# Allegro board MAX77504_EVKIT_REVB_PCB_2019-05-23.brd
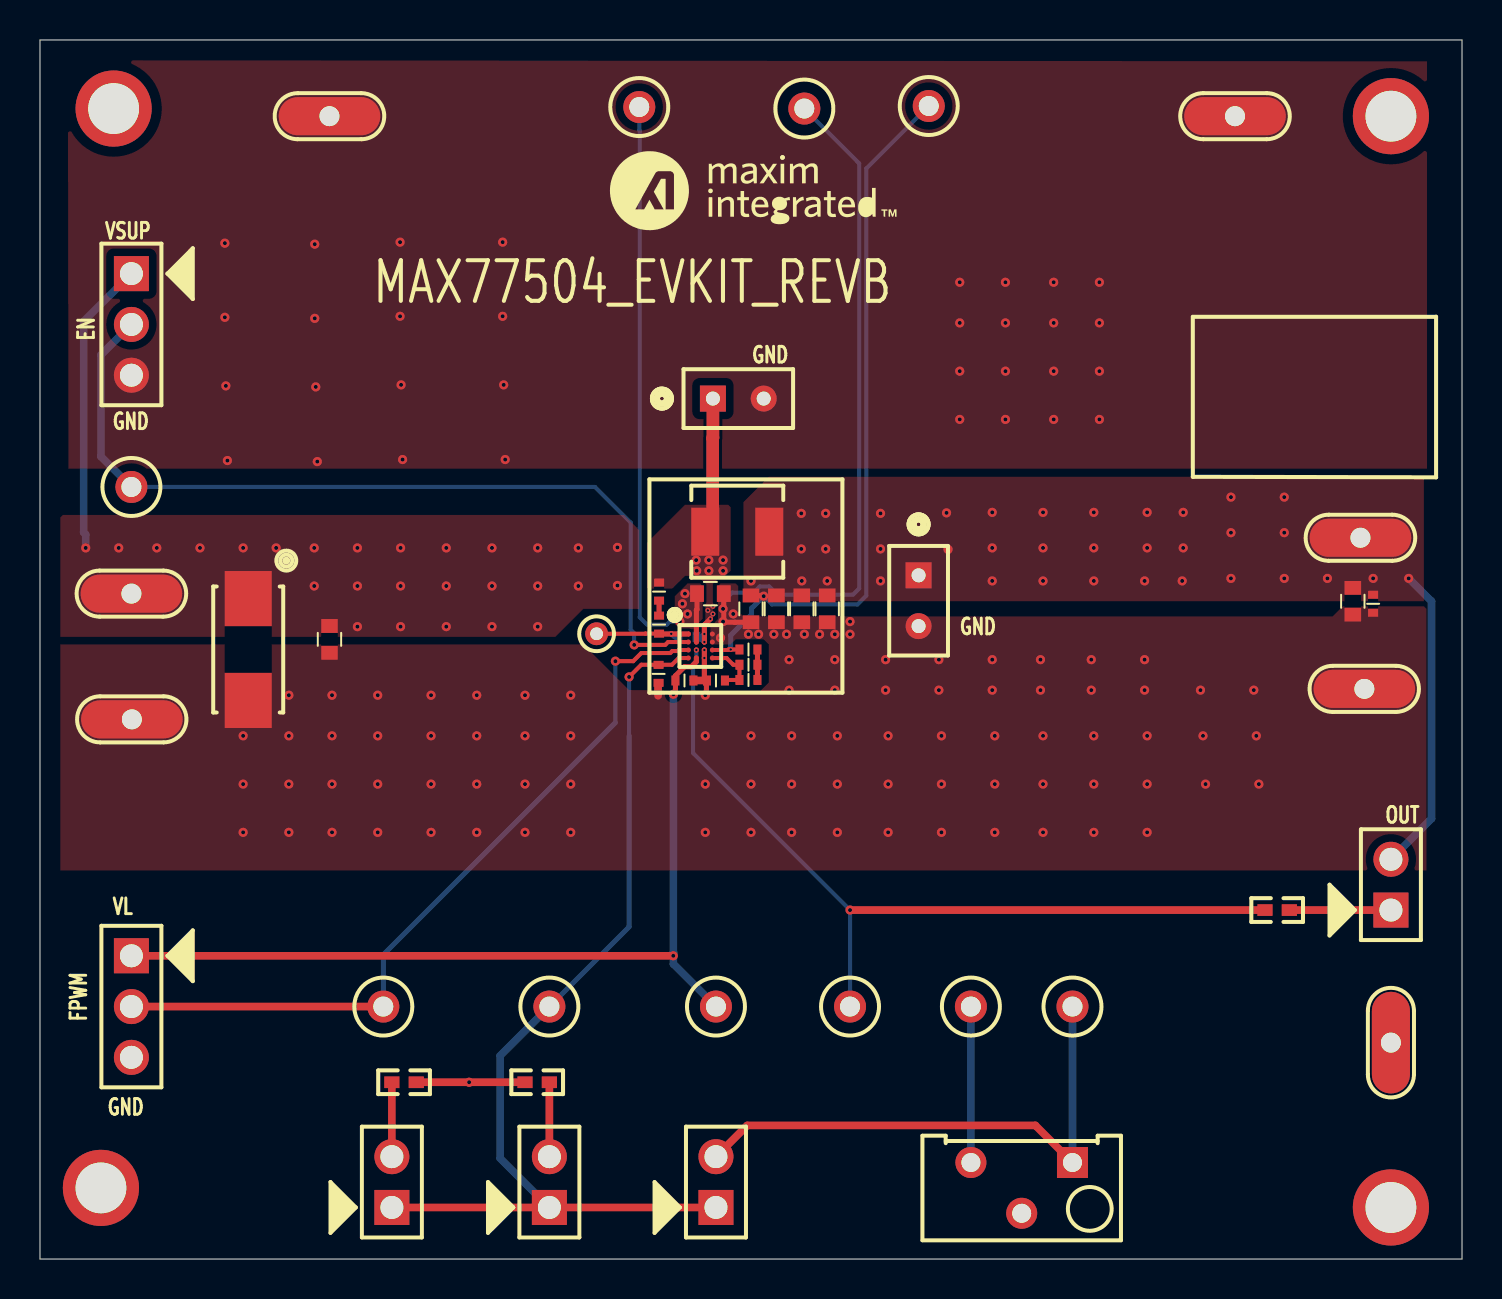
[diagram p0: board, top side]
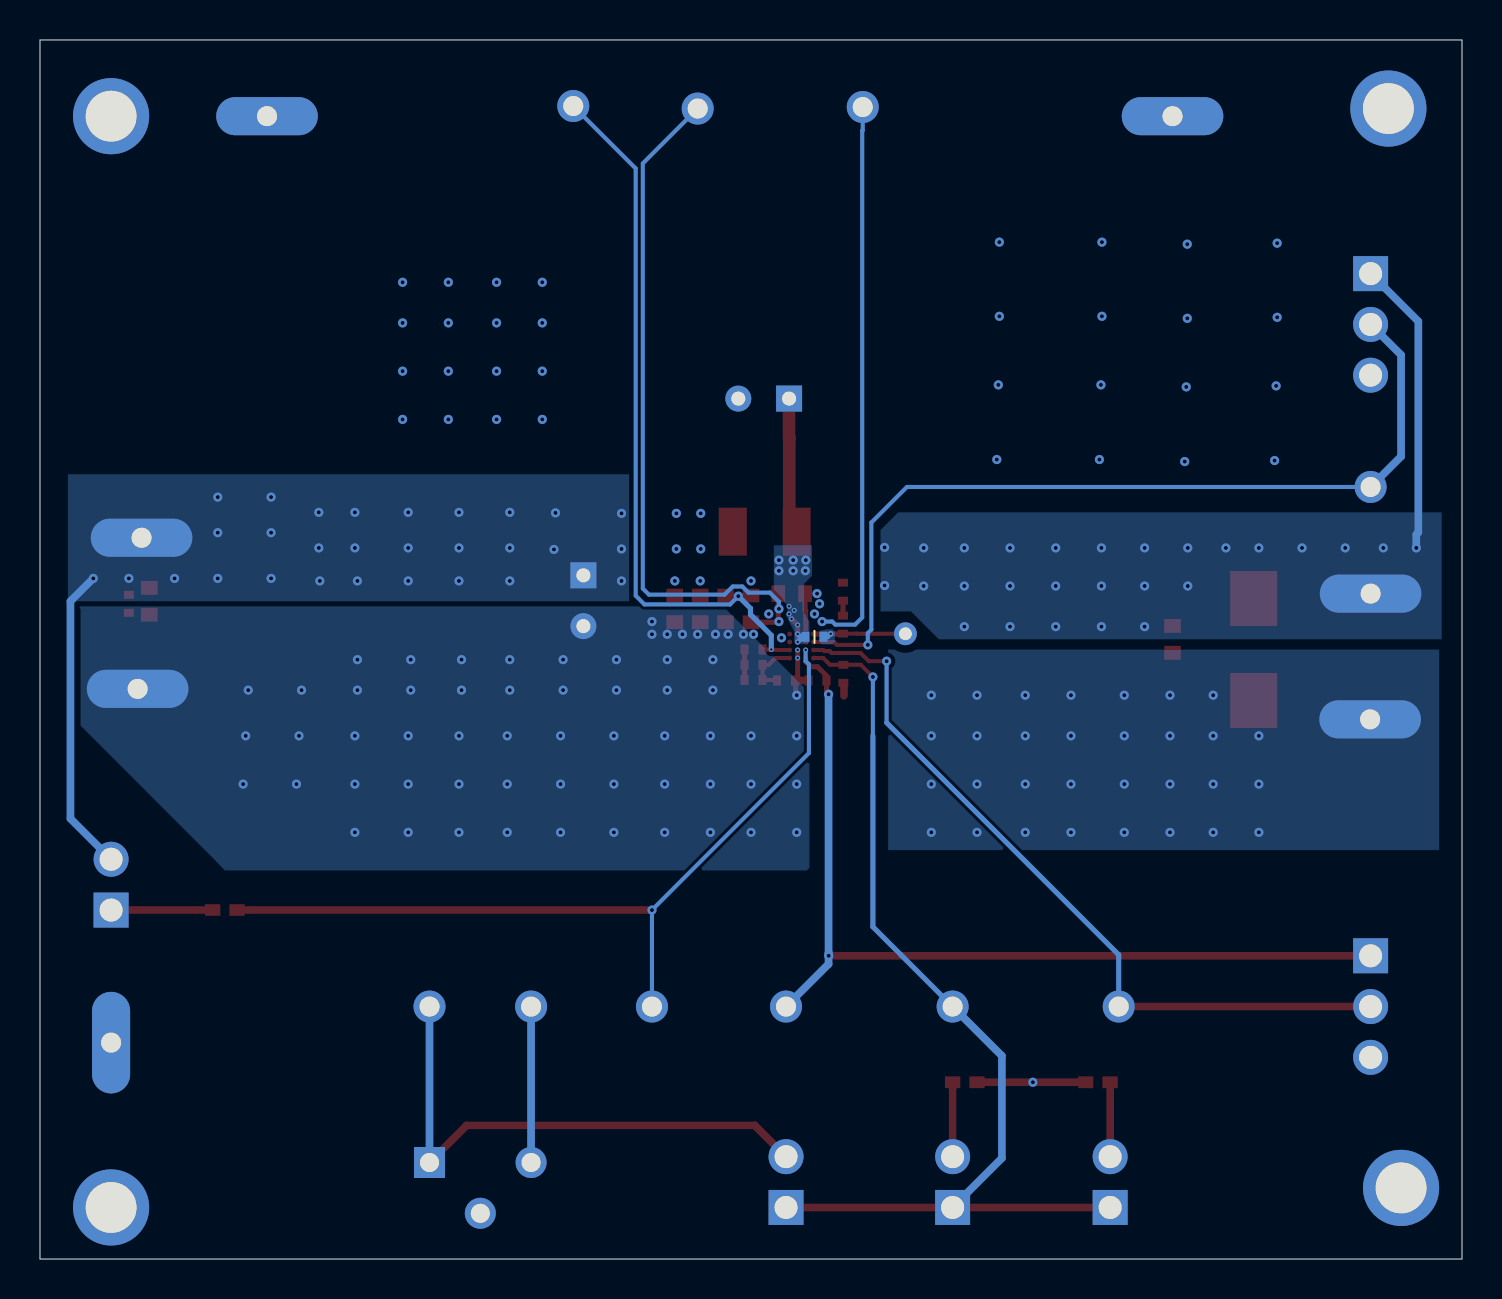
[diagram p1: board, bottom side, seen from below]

Outline 71.12 x 60.96 mm; copper layers: TOP, INTERNAL2, INTERNAL3, BOTTOM. Coordinates in mm from the lower left corner of the outline.
Outline path: 0,60.96 0,0 71.12,0 71.12,60.96 0,60.96

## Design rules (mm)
constraint set DEFAULT: min track width 0.254

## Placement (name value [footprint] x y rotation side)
BST  N/A  [TP_C114H63]  27.84 31.27 0 top
C1  10UF  [0603]  33.53 33.27 180 top
C2  OPEN  [CAPC1608X90L]  14.48 30.99 90 top
C3  2.2UF  [CAPC1005X50L]  32.23 28.93 180 top
C4  2.2PF  [0402]  35.43 29.72 0 top
C5  22UF  [CAPC1608X90L]  35.56 32.51 90 top
C6  22UF  [CAPC1608X90L]  36.83 32.51 90 top
C7  22UF  [CAPC1608X90L]  38.1 32.51 90 top
C8  OPEN  [CAPC1608X90L]  39.37 32.51 90 top
C9  0.1UF  [CAPC1005X50L]  66.67 32.77 90 top
C10  OPEN  [CAPC1608X90L]  65.66 32.89 90 top
C11  100UF  [CAPMP6032X280M]  10.41 30.48 270 top
C12  OPEN  [CAPC1005X50L]  32.38 31.11 180 bottom
C13  0.22UF  [CAPC1005X50L]  30.96 33.38 270 top
EN  N/A  [TP_180P120D460H]  4.57 38.61 0 top
EV_KIT_BOX1  SMALL BOX  [EVKIT_PACKAGING]  12.67 180.68 0 top
FPWM  N/A  [TP_180P120D460H]  17.17 12.62 0 top
GND  MAXIMPAD  [EVK_MAXIMPAD]  4.6 26.99 0 top
GND2  MAXIMPAD  [EVK_MAXIMPAD]  66.24 28.51 0 top
GND3  MAXIMPAD  [EVK_MAXIMPAD]  59.77 57.15 0 top
GND4  MAXIMPAD  [EVK_MAXIMPAD]  14.48 57.15 0 top
GND5  MAXIMPAD  [EVK_MAXIMPAD]  67.56 10.82 90 top
GND6  N/A  [TP_180P120D460H]  46.56 12.62 0 top
GNDS  N/A  [TP_180P120D460H]  38.23 57.53 0 top
J1  TSW-103-07-T-S  [SAMTEC_TSW-103-07-T-S]  4.57 49.28 270 top
J2  TSW-103-07-T-S  [SAMTEC_TSW-103-07-T-S]  4.57 15.16 270 top
J3  TSW-102-07-T-S  [SAMTEC_TSW-102-07-X-S]  33.81 2.58 90 top
J4  TSW-102-07-T-S  [SAMTEC_TSW-102-07-X-S]  25.48 2.58 90 top
J5  TSW-102-07-T-S  [SAMTEC_TSW-102-07-X-S]  17.6 2.58 90 top
J7  TSW-102-07-T-S  [SAMTEC_TSW-102-07-X-S]  67.56 17.45 90 top
L1  1.5UH  [IND_FDSD0412]  34.87 36.37 0 top
LX  SS-102-TT-2  [SMTC_SS-102-XX-2]  33.66 43.03 0 top
NOREF  -  []  30.53 53.34 0 top
NOREF#2  -  []  71.12 0 90 top
NOREF#3  -  [unnamed#2]  3.05 3.56 0 top
NOREF#4  -  []  0 60.96 0 top
NOREF#5  -  [unnamed#2]  3.68 57.53 0 top
NOREF#6  -  []  267.84 -50.16 0 top
NOREF#7  -  [unnamed#2]  67.56 2.58 0 top
NOREF#8  -  []  42.01 128.67 0 top
NOREF#9  -  [unnamed#2]  67.56 57.15 0 top
NOREF#10  -  []  12.7 -12.7 0 top
OUT  MAXIMPAD  [EVK_MAXIMPAD]  66.04 36.07 0 top
OUT1  SS-102-TT-2  [SMTC_SS-102-XX-2]  43.94 34.19 270 top
OUTS  N/A  [TP_180P120D460H]  44.45 57.66 0 top
POK  N/A  [TP_180P120D460H]  40.51 12.62 0 top
POT  N/A  [TP_180P120D460H]  51.64 12.62 0 top
R1  100K  [0402#2]  61.87 17.45 180 top
R2  0  [RESC1005X50L#2]  30.96 31.72 90 top
R3  49.9K  [0402]  35.43 28.96 180 top
R4  11.1K  [0402]  33.81 28.93 180 top
R5  0  [RESC1005X50L#2]  35.43 30.48 180 top
R6  200K  [BOURNS_3296Y]  49.1 3.56 0 top
R7  OPEN  [RESC1005X50L]  24.87 8.84 180 top
R8  OPEN  [RESC1005X50L]  18.21 8.84 0 top
R12  OPEN  [RESC1005X50L#2]  30.94 29.26 270 top
SEL  N/A  [TP_180P120D460H]  25.48 12.62 0 top
SUP  MAXIMPAD  [EVK_MAXIMPAD]  4.57 33.27 0 top
SUPS  N/A  [TP_180P120D460H]  29.97 57.61 0 top
U1  MAX77504AAWE+  [BGA16C40P4X4_168X168X69M]  33.03 30.65 0 top
VL  N/A  [TP_180P120D460H]  33.81 12.62 0 top

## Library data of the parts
BST = TP: part number: TP_TP-TP_C114H63,N/A,N/A
C1 = CAP_NP: alternate symbols: 0603_NOSILK,CAPC1608X90L,CAP0603-NOT_FOR_TEST; part number: CAP_NP_0603CAP-0603,10UF,20-0010U-P7
C2 C8 C10 = EK_CAP_NP: alternate symbols: 0603,0603_NOSILK; part number: EK_CAP_NP_0603_FF-CAPC1608X90L,OPEN,N/A
C3 = EK_CAP_NP: part number: EK_CAP_NP_0402_FF-CAPC1005X50L,2.2UF,20-002U2-19
C4 = CAP_NP: alternate symbols: 0402_NOSILK,CAPC1005X50L,CAP0402-NOT_FOR_TEST; part number: CAP_NP_0402CAP-0402,2.2PF,20-002P2-X1B
C5-C7 = EK_CAP_NP: part number: EK_CAP_NP_0603_FF-CAPC1608X90L,22UF,20-0022U-A48
C9 = EK_CAP_NP: part number: EK_CAP_NP_0402_FF-CAPC1005X50L,0.1UF,20-000U1-33
C11 = CAP_POL: part number: CAP_POL_6032CAP-CAPMP6032X280M,100UF,20-0100U-D6
C12 = EK_CAP_NP: alternate symbols: 0402,0402_NOSILK; part number: EK_CAP_NP_0402_FF-CAPC1005X50L,OPEN,N/A
C13 = EK_CAP_NP: part number: EK_CAP_NP_0402_FF-CAPC1005X50L,0.22UF,20-00U22-B19
EN FPWM POK POT SEL = TP: part number: TP_TP-TP_180P120D460H,N/A,02-TPMINI5002-00
EV_KIT_BOX1 = EV_KIT_BOX: part number: EV_KIT_BOX_ACCESSORY-N/A,SMALL BOX,EVKIT_PACKAGING
GND GND2-GND5 OUT SUP = EVK_MAXIMPAD: alternate symbols: EVK_MAXIMPAD_ALT; part number: EVK_MAXIMPAD_MISC-EVK_MAXIMPAD,MAXIMPAD,01-9020BUSS20AWG-00
GND6 GNDS = TP: part number: TP_TP-TP_180P120D460H,N/A,02-TPMINI5001-00
J1 J2 = HEADER_3P: part number: HEADER_3P_SIP-SAMTEC_TSW-103-07-T-S,TSW-103-07-T-S,01-TSW10307TS3P-17
J3-J5 J7 = HEADER_2P: part number: HEADER_2P_TH-SAMTEC_TSW-102-07-X-S,TSW-102-07-T-S,01-TSW10207TS2P-17
L1 = INDUCT: part number: INDUCT_SMT-IND_FDSD0412,1.5UH,EL111000002739
LX OUT1 = SKT_SIP_2P: part number: SKT_SIP_2P_SIP-SMTC_SS-102-XX-2,SS-102-TT-2,15-100SP02P-02
OUTS SUPS VL = TP: part number: TP_TP-TP_180P120D460H,N/A,02-TPMINI5000-00
R1 = RES: alternate symbols: 0402_NOSILK,RESC1005X50L; part number: RES_0402RES-0402,100K,80-0100K-23
R2 R5 = EK_RES_SMD: part number: EK_RES_SMD_0402_FF-RESC1005X50L,0,80-0000R-26A
R3 = RES: alternate symbols: 0402_NOSILK,RESC1005X50L; part number: RES_0402RES-0402,49.9K,80-049K9-18A
R4 = RES: alternate symbols: 0402_NOSILK,RESC1005X50L,RES0402-NOT_FOR_TEST; part number: RES_0402RES-0402,11.1K,ER111000002752
R6 = RES_POT: part number: RES_POT_POT-BOURNS_3296Y,200K,80-0200K-F0A
R7 R8 R12 = EK_RES_SMD: alternate symbols: 0402,0402_NOSILK,; part number: EK_RES_SMD_0402_FF-RESC1005X50L,OPEN,N/A
U1 = EK_MAX77504: part number: EK_MAX77504_WLP16-BGA16C40P4X4_168X168X69M,MAX77504AAWE+,N/A

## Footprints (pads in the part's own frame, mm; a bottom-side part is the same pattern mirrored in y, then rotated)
0402
  rect 0.4x0.5 smd: 1(-0.45,0) 2(0.45,0)
0402#2
  rect 0.762x0.584 smd: 1(-0.61,0) 2(0.61,0)
0603
  rect 0.69x0.83 smd: 1(-0.67,0) 2(0.67,0)
BGA16C40P4X4_168X168X69M
  round 0.25 smd: A1(-0.6,0.6) A2(-0.2,0.6) A3(0.2,0.6) A4(0.6,0.6) B1(-0.6,0.2) B2(-0.2,0.2) B3(0.2,0.2) B4(0.6,0.2) C1(-0.6,-0.2) C2(-0.2,-0.2) C3(0.2,-0.2) C4(0.6,-0.2) D1(-0.6,-0.6) D2(-0.2,-0.6) D3(0.2,-0.6) D4(0.6,-0.6)
BOURNS_3296Y
  rect 1.55x1.55 hole 0.95: 1(2.54,1.27)
  round 1.55 hole 0.95: 2(0,-1.27) 3(-2.54,1.27)
CAPC1005X50L
  rect 0.4x0.5 smd: 1(-0.45,0) 2(0.45,0)
CAPC1608X90L
  rect 0.69x0.83 smd: 1(-0.67,0) 2(0.67,0)
CAPMP6032X280M
  rect 2.75x2.35 smd: 1(-2.55,0) 2(2.55,0)
EVK_MAXIMPAD
  oval 5.08x1.905 hole 1: 1(0,0)
IND_FDSD0412
  rect 1.4x2.4 smd: 1(-1.6,0) 2(1.6,0)
RESC1005X50L
  rect 0.762x0.584 smd: 1(-0.61,0) 2(0.61,0)
RESC1005X50L#2
  rect 0.4x0.5 smd: 1(-0.45,0) 2(0.45,0)
SAMTEC_TSW-102-07-X-S
  rect 1.75x1.75 hole 1.15: 1(0,0)
  round 1.75 hole 1.15: 2(2.54,0)
SAMTEC_TSW-103-07-T-S
  rect 1.75x1.75 hole 1.15: 1(0,0)
  round 1.75 hole 1.15: 2(2.54,0) 3(5.08,0)
SMTC_SS-102-XX-2
  rect 1.3x1.3 hole 0.7: 1(0,0)
  round 1.3 hole 0.7: 2(2.54,0)
TP_180P120D460H
  round 1.6 hole 1: 1(0,0)
TP_C114H63
  round 1.143 hole 0.635: 1(0,0)
unnamed#2
  round 3.81 hole 2.54: (0,0)

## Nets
BST: BST.1(TP1) C12.2 R2.1 U1.A1
EN: EN.1(TP1) J1.2 U1.B1
FB: C4.1 R3.2 R4.1 U1.D4
FPWM: FPWM.1(TP1) J2.2 U1.C1
GROUND: C1.1 C2.1 C3.1 C5.1 C6.1 C7.1 C8.1 C9.1 C10.1 C11.2(B) GND.1 GND2.1 GND3.1 GND4.1 GND5.1 GND6.1(TP1) GNDS.1(TP1) J1.3 J2.3 LX.2 OUT1.2 R4.2 R6.2 R6.3 R7.2 R8.2 R12.2 U1.A4 U1.B4 U1.C3 U1.D3
LX: C12.1 C13.1 L1.1 LX.1 U1.A3 U1.B3
OUT: C5.2 C6.2 C7.2 C8.2 C9.2 C10.2 J7.2 L1.2 OUT.1 OUT1.1 OUTS.1(TP1) R5.2 U1.C4
POK: POK.1(TP1) R1.2 U1.C2
SEL: J3.1 J4.1 J5.1 R12.1 SEL.1(TP1) U1.D1
UNNAMED_1_CAPNP_I33_2: C4.2 R3.1 R5.1
UNNAMED_1_EKCAPNP_I3_2: C13.2 R2.2
UNNAMED_1_EKRESSMD_I70_1: J4.2 R7.1
UNNAMED_1_EKRESSMD_I71_1: J5.2 R8.1
UNNAMED_1_HEADER2P_I48_1: J7.1 R1.1
UNNAMED_1_HEADER2P_I69_2: J3.2 POT.1(TP1) R6.1
VL: C3.2 J2.1 U1.D2(VL) VL.1(TP1)
VSUP: C1.2 C2.2 C11.1 J1.1 SUP.1 SUPS.1(TP1) U1.A2 U1.B2

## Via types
v1: diameter 0.457, hole 0.203, TOP to BOTTOM, 210 vias
v2: diameter 0.254, hole 0.127, TOP to BOTTOM, 12 vias

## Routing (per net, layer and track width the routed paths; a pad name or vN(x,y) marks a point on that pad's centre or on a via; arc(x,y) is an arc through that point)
BST: length 5
  TOP w0.203: R2.1 30.28,31.27 30.27,31.27 BST.1
  TOP w0.254: R2.1 30.98,31.26 31.56,31.26 v2(31.57,31.27) 31.58,31.26 31.92,31.26 31.92,31.25 U1.A1
  BOTTOM w0.254: v2(31.57,31.27) 31.58,31.26 31.6,31.26 31.74,31.11 C12.2
EN: length 44.1
  TOP w0.203: v1(29.72,30.71) 31.27,30.71 31.41,30.85 U1.B1
  BOTTOM w0.203: EN.1 27.76,38.61 29.54,36.83 29.54,31.47 29.72,31.29 v1(29.72,30.71)
  BOTTOM w0.381: J1.2 3.05,45.21 3.05,40.13 EN.1
FB: length 3
  TOP w0.203: R4.1 34.28,28.96 R3.2 C4.1 34.67,29.72 34.33,30.05 U1.D4
FPWM: length 38.6
  TOP w0.203: U1.C1 31.95,30.45 31.9,30.4 31.62,30.4 31.52,30.3 30.07,30.3 29.67,29.9 v1(28.78,29.9)
  TOP w0.381: J2.2 FPWM.1
  BOTTOM w0.203: 28.78,26.82 v1(28.78,29.9)
  BOTTOM w0.254: 28.78,26.82 17.17,15.21 FPWM.1
GROUND: length 52.6
  TOP w0.203: v1(33.27,28.19) 33.27,28.26 33.33,28.31
  TOP w0.254: 33.33,28.31 33.33,28.91 R4.2 33.23,29.06 v2(33.23,30.05) v2(33.23,30.45) ; C1.1 34.2,31.91 v1(34.16,31.88) 34.2,31.84 34.76,31.84 34.76,31.84 C5.1
  TOP w0.381: R8.2 v1(21.46,8.84) R7.2 ; R12.2 30.91,28.79 30.91,28.17 ; C3.1 R4.2
  BOTTOM w0.203: v1(34.16,32.51) 34.16,32.87 34.62,33.32 35.69,33.32 35.99,33.63 36.47,33.63 36.88,33.22 40.67,33.22 40.97,33.53 40.97,54.79 GNDS.1
  BOTTOM w0.381: R6.3 GND6.1
  vias: v1(9.25,50.8) v1(9.25,47.09) v1(9.3,43.66) v1(9.37,39.93) v1(10.16,26.16) v1(10.16,23.75) v1(10.16,21.34) v1(12.45,28.19) v1(12.45,26.16) v1(12.45,23.75) v1(12.45,21.34) v1(13.74,50.75) v1(13.74,47.04) v1(13.79,43.61) v1(13.87,39.88) v1(14.61,28.19) v1(14.61,26.16) v1(14.61,23.75) v1(14.61,21.34) v1(16.89,28.19) v1(16.89,26.16) v1(16.89,23.75) v1(16.89,21.34) v1(18.01,50.85) v1(18.01,47.14) v1(18.06,43.71) v1(18.14,39.98) v1(19.56,28.19) v1(19.56,26.16) v1(19.56,23.75) v1(19.56,21.34) v1(21.84,28.19) v1(21.84,26.16) v1(21.84,23.75) v1(21.84,21.34) v1(23.14,50.85) v1(23.14,47.14) v1(23.19,43.71) v1(23.27,39.98) v1(24.26,28.19) v1(24.26,26.16) v1(24.26,23.75) v1(24.26,21.34) v1(26.54,28.19) v1(26.54,26.16) v1(26.54,23.75) v1(26.54,21.34) v1(33.27,26.16) v1(33.27,23.75) v1(33.27,21.34) v1(34.04,31.06) v1(34.67,32.26) v1(35.43,31.24) v1(35.56,26.16) v1(35.56,23.75) v1(35.56,21.34) v1(35.94,31.24) v1(36.7,31.24) v1(37.34,31.24) v1(37.47,29.97) v1(37.47,28.45) v1(37.59,26.16) v1(37.59,23.75) v1(37.59,21.34) v1(38.23,31.24) v1(38.99,31.24) v1(39.75,31.24) v1(39.75,29.97) v1(39.75,28.45) v1(39.88,26.16) v1(39.88,23.75) v1(39.88,21.34) v1(40.51,31.88) v1(40.51,31.24) v1(42.29,29.97) v1(42.29,28.45) v1(42.42,26.16) v1(42.42,23.75) v1(42.42,21.34) v1(44.96,29.97) v1(44.96,28.45) v1(45.09,26.16) v1(45.09,23.75) v1(45.09,21.34) v1(46,48.84) v1(46,46.81) v1(46,44.4) v1(46,41.99) v1(47.62,29.97) v1(47.62,28.45) v1(47.75,26.16) v1(47.75,23.75) v1(47.75,21.34) v1(48.29,48.84) v1(48.29,46.81) v1(48.29,44.4) v1(48.29,41.99) v1(50.04,29.97) v1(50.04,28.45) v1(50.16,26.16) v1(50.16,23.75) v1(50.16,21.34) v1(50.7,48.84) v1(50.7,46.81) v1(50.7,44.4) v1(50.7,41.99) v1(52.58,29.97) v1(52.58,28.45) v1(52.7,26.16) v1(52.7,23.75) v1(52.7,21.34) v1(52.98,48.84) v1(52.98,46.81) v1(52.98,44.4) v1(52.98,41.99) v1(55.24,29.97) v1(55.24,28.45) v1(55.37,26.16) v1(55.37,23.75) v1(55.37,21.34) v1(58.04,28.45) v1(58.17,26.16) v1(58.29,23.75) v1(60.71,28.45) v1(60.83,26.16) v1(60.96,23.75)
LX: length 8
  TOP w0.254: v2(33.53,32.01) v2(33.23,31.71) v2(33.23,31.25) v2(33.23,30.85)
  TOP w0.635: LX.1 33.66,41.07 33.64,41.06 33.64,37.08
  BOTTOM w0.254: 32.97,31.11 C12.1 ; 32.97,31.11 33.09,31.11 v2(33.23,31.25) ; 32.97,31.11 v2(33.23,30.85)
  vias: v1(32.82,34.95) v1(32.84,34.42) v1(33.45,34.95) v1(33.45,34.42) v1(34.16,34.95) v1(34.16,34.42) v2(33.4,32.44) v2(33.66,32.64) v2(33.66,32.26)
OUT: length 52
  TOP w0.203: U1.C4 34.4,30.45 34.43,30.48 v2(34.54,30.48) R5.2
  TOP w0.254: C5.2 36.16,33.18 v1(36.2,33.15)
  BOTTOM w0.203: v1(36.2,33.15) 36.61,32.73 40.89,32.73 41.33,33.17 41.33,54.53 OUTS.1
  BOTTOM w0.254: v2(34.54,30.48) 34.54,31.19 35.59,32.23 35.59,32.54 v1(36.2,33.15)
  BOTTOM w0.381: v1(68.45,34.04) 69.6,32.89 69.6,22.02 J7.2
  vias: v1(35.56,33.91) v1(38.07,37.29) v1(38.07,35.51) v1(38.1,33.91) v1(39.29,37.29) v1(39.29,35.51) v1(39.37,33.91) v1(42.04,37.29) v1(42.04,35.51) v1(42.04,33.91) v1(45.34,37.31) v1(45.42,35.48) v1(47.62,37.34) v1(47.62,35.56) v1(47.62,33.91) v1(50.16,37.34) v1(50.16,35.56) v1(50.16,33.91) v1(52.7,37.34) v1(52.7,35.56) v1(52.7,33.91) v1(55.24,33.91) v1(55.37,37.34) v1(55.37,35.56) v1(57.12,33.91) v1(57.18,37.34) v1(57.18,35.56) v1(59.56,38.1) v1(59.56,36.32) v1(59.56,34.04) v1(62.23,38.1) v1(62.23,36.32) v1(62.23,34.04) v1(64.39,34.04) v1(66.67,34.04)
POK: length 41.9
  TOP w0.381: R1.2 v1(40.51,17.45)
  BOTTOM w0.203: POK.1 v1(40.51,17.45) 32.66,25.3 32.66,29.74 32.83,29.91 v2(32.83,30.45)
SEL: length 49.8
  TOP w0.203: 30.93,29.72 30.07,29.72 v1(29.46,29.11) ; 30.93,29.72 31.61,29.72 31.95,30.05 U1.D1 ; 30.93,29.72 R12.1
  TOP w0.381: J5.1 J4.1 J3.1
  BOTTOM w0.203: 29.46,26.16 v1(29.46,29.11)
  BOTTOM w0.254: SEL.1 29.46,16.61 29.46,26.16
  BOTTOM w0.381: J4.1 23.01,5.04 23.01,10.16 SEL.1
UNNAMED_1_CAPNP_I33_2: length 1.5
  TOP w0.254: R5.1 C4.2 R3.1
UNNAMED_1_EKCAPNP_I3_2: length 0.8
  TOP w0.254: R2.2 C13.2
UNNAMED_1_EKRESSMD_I70_1: length 3.7
  TOP w0.381: R7.1 J4.2
UNNAMED_1_EKRESSMD_I71_1: length 3.7
  TOP w0.381: R8.1 J5.2
UNNAMED_1_HEADER2P_I48_1: length 5.1
  TOP w0.381: R1.1 J7.1
UNNAMED_1_HEADER2P_I69_2: length 27
  TOP w0.381: J3.2 35.37,6.68 49.78,6.68 R6.1
  BOTTOM w0.381: POT.1 R6.1
VL: length 46.2
  TOP w0.254: U1.D2 32.83,29.87 32.57,29.62 32.23,29.62 31.78,29.17 C3.2 31.78,28.34 v1(31.68,28.24)
  TOP w0.381: J2.1 v1(31.67,15.16)
  BOTTOM w0.381: v1(31.67,15.16) 31.67,15.31 31.68,15.32 ; 31.68,15.32 v1(31.68,28.24) ; 31.68,15.32 31.68,14.75 VL.1
VSUP: length 44.9
  TOP w0.254: C1.2 32.86,32.48 32.83,32.45 U1.A2 U1.B2
  BOTTOM w0.203: SUPS.1 29.97,56.45 30,56.43 30,32.08 30.35,31.72 31.34,31.72 31.5,31.88 v1(32,31.88)
  BOTTOM w0.381: v1(2.29,35.56) 2.29,36.23 2.18,36.33 2.18,46.89 J1.1
  vias: v1(3.94,35.56) v1(5.84,35.56) v1(8,35.56) v1(10.16,35.56) v1(11.81,35.56) v1(13.72,35.56) v1(13.72,33.66) v1(15.88,35.56) v1(15.88,33.66) v1(15.88,31.62) v1(18.03,35.56) v1(18.03,33.66) v1(18.03,31.62) v1(20.32,35.56) v1(20.32,33.66) v1(20.32,31.62) v1(22.61,35.56) v1(22.61,33.66) v1(22.61,31.62) v1(24.89,35.56) v1(24.89,33.66) v1(24.89,31.62) v1(26.92,35.56) v1(26.92,33.66) v1(28.88,35.59) v1(28.88,33.68) v1(32.13,32.77) v1(32.26,33.27) v1(32.38,32.26)

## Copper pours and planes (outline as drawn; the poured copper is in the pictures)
GROUND on TOP: 34.04,33.78 34.8,33.78 34.92,33.66 34.92,32.38 35.18,32.13 64.64,32.13 65.15,32.64 69.22,32.64 69.34,32.51 69.34,19.43 1.02,19.43 1.02,30.73 27.18,30.73 29.46,28.45 36.07,28.45 36.45,28.83 36.45,30.73 36.2,30.99 34.8,30.99 34.54,30.73 33.66,30.73 33.53,30.86 33.53,31.62 33.91,32 33.91,33.66
GROUND on TOP: 1.4,59.94 1.42,39.52 69.37,39.52 69.37,59.89 ; 2 cut-outs
GROUND on BOTTOM: 1.14,30.48 1.14,20.45 28.7,20.45 28.7,30.48
GROUND on BOTTOM: 32.64,28.32 32.64,19.56 32.77,19.43 61.87,19.43 62.48,20.07 69.09,26.67 69.09,32.51 69.22,32.64 36.96,32.64
GROUND on INTERNAL2: 0.64,59.94 0.64,0.64 70.36,0.64 70.36,59.94 ; 4 cut-outs
GROUND on INTERNAL3: 0.89,59.82 0.89,0.51 70.23,0.51 70.23,59.82 ; 4 cut-outs
LX on TOP: 34.42,37.72 34.54,37.59 34.54,34.42 33.78,33.66 33.78,32.13 33.27,31.62 33.27,33.78 32.89,34.16 32.26,34.16 31.62,33.53 30.35,33.53 30.35,35.81 32.26,37.72
LX on BOTTOM: 32.64,30.73 33.4,30.73 33.4,31.37 34.42,33.4 34.42,35.69 32.51,35.69 32.51,34.16 32.89,33.78 32.89,32.26 32.64,32
LX on INTERNAL3: 32.51,35.56 34.42,35.56 34.42,33.4 33.91,32.89 33.91,31.11 33.53,30.73 33.02,30.73 32.89,30.86 32.89,33.53 32.51,33.91
OUT on TOP: 35.18,37.85 35.18,32.89 69.22,32.89 69.22,39.12 36.45,39.12
OUT on BOTTOM: 41.66,39.24 41.66,32.89 69.72,32.89 69.72,39.24
OUT on INTERNAL3: 36.45,39.12 35.18,37.85 35.18,33.27 35.43,33.02 35.81,33.02 36.32,32.51 68.83,32.51 69.22,32.89 69.09,39.12
VSUP on TOP: 1.14,37.21 29.21,37.21 29.97,36.45 29.97,32.51 27.18,32.51 25.78,31.11 1.02,31.11 1.02,37.08
VSUP on TOP: 33.15,33.66 33.15,32 32.89,31.75 32.89,31.5 32,31.5 31.75,31.75 31.75,33.15 32.38,33.78 33.02,33.78
VSUP on BOTTOM: 1.02,37.34 1.02,30.99 26.16,30.99 27.56,32.38 29.08,32.38 29.08,36.45 28.19,37.34
VSUP on INTERNAL3: 1.02,37.08 30.86,37.08 32.64,35.31 32.64,31.5 29.21,31.5 28.7,30.99 1.14,30.99 1.02,31.11

Small or netless copper shapes (teardrops, artwork), in the pictures only: 1 on BOTTOM

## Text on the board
Ref Des/Silkscreen Top: VSUP | GND | VL | OUT | FPWM | EN | MAX77504_EVKIT_REVB
User.9: NOTES: | SURFACE FINISH: | TESTING: | SOLDERMASK: | MISCELLANEOUS: | SILKSCREEN: | MATERIAL: | TOOLING: | 16.  VENDOR LOGO & DATE CODE REQUIREMENT.  DATE CODE FORMAT MUST BE YYWW ONLY | 17.  FINAL ELECTRICAL TEST TO BE PERFORMED USING PROVIDED IPC-D-356A NETLIST OR ODB++ FORMAT FILE. | 18.  A TIME DOMAIN REFLECTOMETER REPORT FOR EACH IMPEDANCE CONTROLLED LAYER AND A CERTIFICATE | 19. IF PRESENT, ALL BLIND/BURIED VIAS WITH AN ASPECT RATIO <1:1 TO BE PLATED SHUT WITH COPPER WHEN | 20.  FOR ALL DRILL INFORMATION REFER TO DRILL CHART. | 21.  FINISHED SURFACE CONTACTS AND FILLED VIAS TO BE FREE OF ANY PITS. SCRATCHES PROBE MARKS | 23.  PEMNUT | 14.  SOLDERMASK OVER BARE COPPER OR BARE GOLD (BOTH SIDES) WITH LIQUID PHOTO IMAGEABLE (LPI) INK | 13.  DRILL SIZES ARE FINISHED HOLE SIZES. ALL HOLES SHALL BE LOCATED WITHIN .005 DTP. | 22.  THIEVING: | 9.  ALL TRACES FILLETED OPTION TO ENHANCE RELIABILITY AT PAD JUNCTIONS | 10.  LAYER TO LAYER REGISTRATIONS SHALL BE WITHIN .003 INCHES. | 15. APPLY SILKSCREEN USING A NON-CONDUCTIVE EPOXY INK | 11.  FINISHED COPPER WEIGHT/THICKNESS: | 12. USE CHECKED ITEMS FOR PLATING | 3.  THE PCB SHALL BE FABRICATED TO IPC-6012, TYPE X, CLASS 2. | 4.  BOARD MATERIAL & CONSTRUCTION SHALL MEET THE REQUIREMENTS OF UL796 | 5.  OVERALL BOARD THICKNESS REFER TO LAMINATION DIAGRAM. TOLERANCE APPLIES | 6.  BOW & TWIST NOT TO EXCEED 0.0075 IN. (0.75%) PER LINEAR INCH. | 7.  PHOTO ETCH CIRCUITRY PER ENCLOSED GERBER RS274X OR ODB++ FORMAT FILE. | 8.  IMPEDANCE REQUIREMENTS: IF NO STACKUP IS DEFINED, THE VENDOR IS ALLOWED TO ADJUST THE DIELECTRIC | 1.  DIMENSIONS ARE IN INCHES (EXCEPT WHERE NOTED). | 2.  BOARD MATERIAL: | (x)  FINISH CONDUCTOR SURFACES: IMMERSION GOLD, 2-5 MICRO INCHES OVER | (X)  WHITE | ( )  OTHER ________________________ | ( )  FINGERS TO BE GOLD PLATED. | ( )  LEAD FREE AND RoHS COMPLIANT PLATING (DO NOT USE OSP) | (X)  REFER TO LAMINATION DIAGRAM FOR FINISHED COPPER WEIGHT/THICKNESS REQUIREMENTS. | (X)  PLACE ON BOTTOM LEGEND LAYER. IF NO BOTTOM LEGEND SUPPLIED, CREATE BOTTOM LEGEND LAYER TO ADD. | ( )  PLACE ON TOP LEGEND LAYER. IF NO TOP LEGEND SUPPLIED,CREATE TOP LEGEND LAYER TO ADD. | ( )  ELECTRODEPOSITED HARD GOLD PLATE, TYPE 1 (99.7% MIN GOLD), GRADE C | (X)  CUSTOM MAXIM TEAL SOLDER MASK. PANTONE #326C. | MINIMUM BARREL PLATING OF .001 IN. PLATED HOLES SHALL NOT BE ROUGH OR IRREGULAR SO AS TO | HINDER PROPER SOLDER WICKING. BARREL RELIEF ON SOLDERMASK ALLOWED ON UNFILLED VIA IN PAD HOLES. | USED AS VIA-IN PAD OR AS A STACKED VIA. BLIND/BURIED VIAS WITH AN ASPECT RATIO >1:1 TO BE FILLED | WITH NON-CONDUCTIVE EPOXY. UNLESS OTHERWISE SPECIFIED. | ( )  NON-CONDUCTIVE EPOXY. FILL AND CAP ALL 0.XXXX INCH DRILLED VIAS. | (x)  SILVER. FILL AND CAP ALL 0.005 INCH DRILLED VIAS. | (REQUIRED UNLESS OTHERWISE SPECIFIED IN QUOTE) | THE PCB SHALL HAVE A VERIFICATION STAMP. | OR OTHER DEFORMITIES THAT COULD EFFECT THE APPERANCE AND PERFORMACE OF THE CONTACT | SURFACE. CONTACTS ARE TO BE AS FLAT AS POSSIBLE. NOT TO EXCEED +/- 0.001" OF FLATNESS. | OF COMPLIANCE SHALL BE PROVIDED BY VENDOR AT TIME OF SHIPMENT. INSTANCES WHERE TDR TESTING | CAN'T BE PERFORMED BECAUSE THE TRACE LENGTH IS TOO SHORT ON THE OUTER LAYERS AT THE PIN ESCAPES | IS ACCEPTABLE, ALL OTHER INSTANCES MUST BE REPORTED. | ( )  SUPPLIER MAY ADD THIEVING TO COMPENSATE FOR LOW COPPER DENSITY AREAS ON THIS DESIGN. | WHERE SPACING PERMITS. | LEGEND TO LEGEND +/- 0.007 INCHES | (X)  SUPPLIER MAY NOT ADD THIEVING TO COMPENSATE FOR LOW COPPER DENSITY AREAS ON THIS DESIGN. | ( )  PEMNUTS TO BE INSTALLED BY FABRICATOR.. | ( )  PEMNUTS NOT TO BE INSTALLED BY FABRICATOR. | (X)  NOT APPLICABLE. | ( )  FILLETED | (X)  NOT FILLETED | (X)  ISOLA 370HR OR EQUIVALENT | ( )  NELCO-4000-13 | ( )  MEGTRON 6 | ( )  ROGERS 4350B | ( )  ROGERS 4003C | ( )  ISOLA-FR408HR OR EQUIVALENT | WORKMANSHIP SHALL CONFORM TO IPC-A-600, CLASS 2, CURRENT REVISIONS. | WITH FLAMMABILITY RATING OF 94V-O. | AFTER ALL LAMINATION AND PLATING PROCESSES. IT IS TO BE MEASURED FROM | TOP PCB METAL TO BOTTOM PCB METAL UNLESS OTHERWISE SPECIFIED. | BOW & TWIST SHOULD BE MEASURED PER IPC-TM-650, METHOD 2.4.22. | DRILL LOCATION AND SIZE CONTROLLED BY EXCELLON CNC DRILL FILE. | THICKNESS AND TRACE WIDTHS TO MEET THE IMPEDANCE REQUIREMENT. IF SPECIFIED, VENDOR MUST FOLLOW AND | MEET THE REQUIREMENTS LISTED IN THE IMPEDANCE TABLE. ANY ADJUSTMENTS MADE TO THE DEFINED STACKUP, | TRACE WIDTH & SPACING THAT IMPACT THE REQUIREMENTS MUST HAVE WRITTEN APPROVAL FROM MAXIM. | UNLESS OTHERWISE SPECIFIED | (USE CHECKED ITEMS FOR MATERIAL) | (KNOOP HARDNESS 130-200), CLASS 1 (50-100 MICRO INCHES THICK) IN ACCORDANCE WITH MIL-G-45204C. | GENERAL SURFACING REQUIREMENTS MUST MEET ANSI/IPC-A-600(CURRENT REV) SECTION 4.0, | CLASS 3 (50-100 MICROINCHES THICK) OVER ELECTRODEPOSITED NICKEL PLATE | IN ACCORDANCE WITH ANSI/IPC-A-600D, SECTION 4.0, CLASS 3 (200-600 MICROINCHES THICK). | 118-236 MICRO INCHES MINIMUM OF ELECTROLESS NICKEL. | THE STARTING COPPER WEIGHT/THICKNESS CAN VARY AS LONG AS THE FINISHED COPPER | WEIGHT/THICKNESS IS NOT LESS THAN THE SPECIFIED VALUE, UNLESS OTHERWISE SPECIFIED. | UNLESS OTHERWISE SPECIFIED:
User.33: FIGURE | SIZE | 5.0 | 8.0 | 25.0 | 27.56 | 37.4 | 39.37 | 45.28 | 100.0 | TOLERANCE | +3.0/-3.0 | +3.0/-6.0 | PLATED | ALL UNITS ARE IN MILS | QTY | 12 | 210 | 1 | 4 | 3 | 24 | 14 | NOTES | DRILL CHART: TOP to BOTTOM
